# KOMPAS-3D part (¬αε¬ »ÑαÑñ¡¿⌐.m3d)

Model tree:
1. Эскиз:1
2. Операция выдавливания:1
     Расстояние 1 = 1; Расстояние 2 = 1
3. Скругление:1
     Радиус = 0.3
4. Скругление:2
     Радиус = 0.6
5. Скругление:3
     Радиус = 0.6
6. Эскиз:2
7. Операция выдавливания:2
     Расстояние 1 = 1; Расстояние 2 = 1
8. Скругление:4
     Радиус = 0.6
9. Скругление:5
     Радиус = 0.6
10. Скругление:6
     Радиус = 0.3
11. Эскиз:3
12. Операция выдавливания:3
     Расстояние 1 = 0.1; Расстояние 2 = 1
13. Эскиз:4
14. Операция выдавливания:4
     Расстояние 1 = 0.7; Расстояние 2 = 0.7
15. Эскиз:5
16. Операция выдавливания:5
     Расстояние 1 = 0.5; Расстояние 2 = 0.5

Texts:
  Сплав АЛ8  ГОСТ 1583-93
